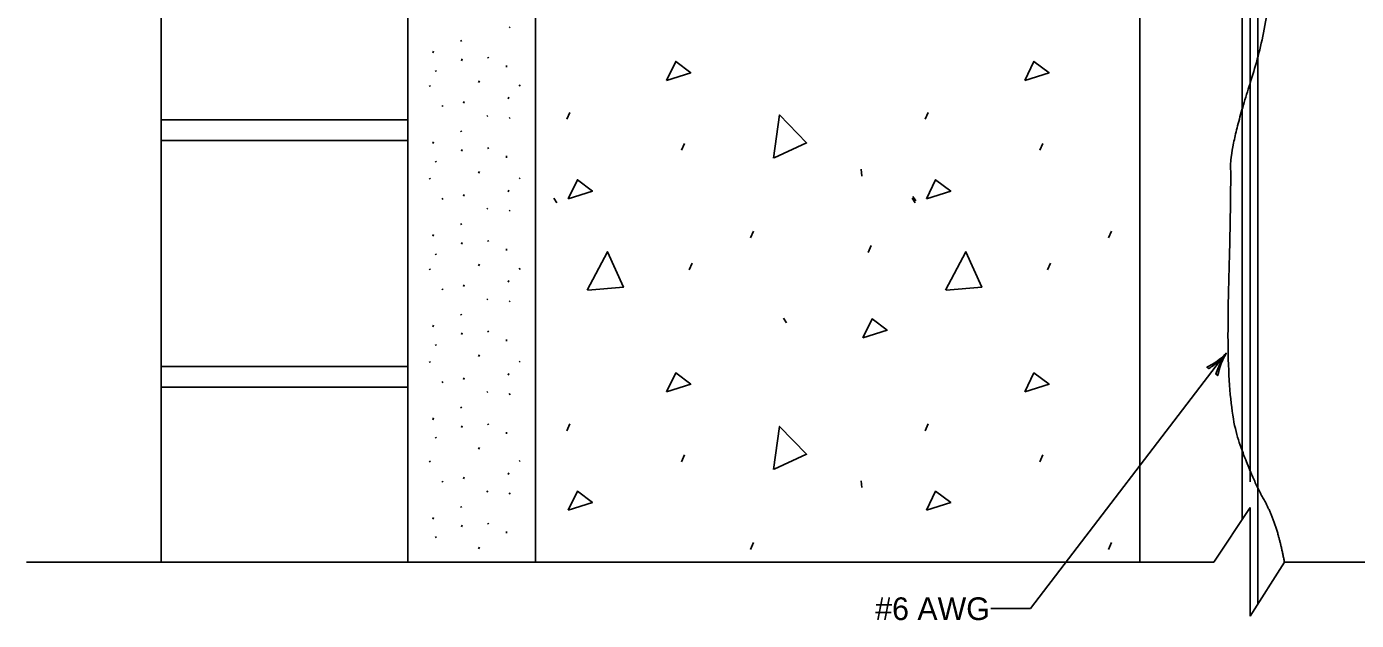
# Model space of a CAD drawing. Extents: x 10099 to 10284, y 10005 to 10185.
# Drawn here: x 10203.12 to 10242.19, y 10078.98 to 10096.42 of the extents above; entities that cross this region are included whole.
import ezdxf

# ---------------------------------------------------------------- set-up
doc = ezdxf.new("R2010")
doc.units = 0
for name, color, linetype in [('Level 46', 7, 'Continuous'), ('Level 5', 7, 'Continuous'), ('Level 6', 7, 'Continuous')]:
    doc.layers.add(name, color=color, linetype=linetype)

msp = doc.modelspace()

# ---------------------------------------------------------------- linework, layer by layer
at = {"layer": 'Level 46'}
for p, q in [((10239.074, 10083.046), (10239.074, 10161.024)), ((10207.074, 10122.686), (10207.074, 10080.693)), ((10214.324, 10122.686), (10214.324, 10080.693)), ((10218.074, 10122.686), (10218.074, 10080.693)), ((10217.302, 10096.418), (10217.325, 10096.384)), ((10215.879, 10096.023), (10215.901, 10095.99)), ((10215.054, 10095.651), (10215.076, 10095.701)), ((10215.897, 10095.423), (10215.919, 10095.473)), ((10216.667, 10095.531), (10216.689, 10095.497)), ((10217.217, 10095.284), (10217.222, 10095.234)), ((10215.134, 10095.137), (10215.157, 10095.103)), ((10216.402, 10094.779), (10216.424, 10094.829)), ((10214.959, 10094.698), (10214.981, 10094.665)), ((10217.596, 10094.711), (10217.618, 10094.677)), ((10215.331, 10094.107), (10215.354, 10094.073)), ((10215.953, 10094.172), (10215.975, 10094.222)), ((10217.268, 10094.299), (10217.29, 10094.349)), ((10207.074, 10093.686), (10214.324, 10093.686)), ((10216.646, 10093.816), (10216.669, 10093.783)), ((10217.302, 10093.756), (10217.325, 10093.723)), ((10218.991, 10093.7), (10219.08, 10093.9)), ((10229.519, 10093.7), (10229.608, 10093.9)), ((10215.879, 10093.362), (10215.901, 10093.329)), ((10207.074, 10093.078), (10214.324, 10093.078)), ((10215.054, 10092.989), (10215.076, 10093.039)), ((10216.667, 10092.869), (10216.689, 10092.836)), ((10222.366, 10092.79), (10222.454, 10092.99)), ((10232.893, 10092.79), (10232.982, 10092.99)), ((10215.134, 10092.475), (10215.157, 10092.442)), ((10215.897, 10092.762), (10215.919, 10092.812)), ((10217.217, 10092.623), (10217.222, 10092.573)), ((10216.402, 10092.118), (10216.424, 10092.168)), ((10227.644, 10092.232), (10227.666, 10092.033)), ((10214.959, 10091.972), (10214.981, 10091.939)), ((10217.596, 10091.985), (10217.618, 10091.951)), ((10215.331, 10091.381), (10215.354, 10091.347)), ((10215.953, 10091.446), (10215.975, 10091.495)), ((10217.268, 10091.573), (10217.29, 10091.623)), ((10218.614, 10091.385), (10218.702, 10091.251)), ((10229.141, 10091.385), (10229.23, 10091.251)), ((10229.159, 10091.435), (10229.248, 10091.302)), ((10216.646, 10091.09), (10216.669, 10091.057)), ((10217.302, 10091.03), (10217.325, 10090.997)), ((10215.879, 10090.636), (10215.901, 10090.603)), ((10215.054, 10090.263), (10215.076, 10090.313)), ((10216.667, 10090.143), (10216.689, 10090.11)), ((10224.386, 10090.215), (10224.475, 10090.415)), ((10234.913, 10090.215), (10235.002, 10090.415)), ((10215.134, 10089.749), (10215.157, 10089.716)), ((10215.897, 10090.036), (10215.919, 10090.086)), ((10217.217, 10089.896), (10217.222, 10089.846)), ((10227.849, 10089.789), (10227.938, 10089.989)), ((10216.402, 10089.392), (10216.424, 10089.442)), ((10222.588, 10089.279), (10222.676, 10089.479)), ((10233.115, 10089.279), (10233.204, 10089.479)), ((10214.959, 10089.311), (10214.981, 10089.277)), ((10217.268, 10088.912), (10217.29, 10088.962)), ((10217.596, 10089.323), (10217.618, 10089.29)), ((10215.331, 10088.72), (10215.354, 10088.686)), ((10215.953, 10088.784), (10215.975, 10088.834)), ((10216.646, 10088.429), (10216.669, 10088.396)), ((10217.302, 10088.369), (10217.325, 10088.336)), ((10215.879, 10087.975), (10215.901, 10087.942)), ((10225.363, 10087.858), (10225.452, 10087.725)), ((10215.054, 10087.602), (10215.076, 10087.652)), ((10215.897, 10087.375), (10215.919, 10087.425)), ((10216.667, 10087.482), (10216.689, 10087.449)), ((10215.134, 10087.088), (10215.157, 10087.055)), ((10217.217, 10087.235), (10217.222, 10087.185)), ((10216.402, 10086.731), (10216.424, 10086.781)), ((10232.617, 10079.33), (10238.328, 10086.789)), ((10207.074, 10086.436), (10214.324, 10086.436)), ((10214.959, 10086.585), (10214.981, 10086.551)), ((10217.268, 10086.186), (10217.29, 10086.236)), ((10217.596, 10086.597), (10217.618, 10086.564)), ((10207.074, 10085.828), (10214.324, 10085.828)), ((10215.331, 10085.993), (10215.354, 10085.96)), ((10215.953, 10086.058), (10215.975, 10086.108)), ((10216.646, 10085.703), (10216.669, 10085.67)), ((10217.302, 10085.643), (10217.325, 10085.61)), ((10215.879, 10085.249), (10215.901, 10085.216)), ((10215.054, 10084.876), (10215.076, 10084.926)), ((10215.897, 10084.649), (10215.919, 10084.699)), ((10216.667, 10084.756), (10216.689, 10084.723)), ((10218.991, 10084.55), (10219.08, 10084.75)), ((10229.519, 10084.55), (10229.608, 10084.75)), ((10215.134, 10084.362), (10215.157, 10084.329)), ((10217.217, 10084.509), (10217.222, 10084.459)), ((10216.402, 10084.005), (10216.424, 10084.055)), ((10214.959, 10083.664), (10214.981, 10083.631)), ((10217.596, 10083.677), (10217.618, 10083.643)), ((10222.366, 10083.64), (10222.454, 10083.84)), ((10232.893, 10083.64), (10232.982, 10083.84)), ((10215.953, 10083.138), (10215.975, 10083.187)), ((10217.268, 10083.265), (10217.29, 10083.315)), ((10215.331, 10083.073), (10215.354, 10083.039)), ((10216.646, 10082.782), (10216.669, 10082.749)), ((10217.302, 10082.722), (10217.325, 10082.689)), ((10227.644, 10083.082), (10227.666, 10082.883)), ((10215.879, 10082.328), (10215.901, 10082.295)), ((10215.054, 10081.955), (10215.076, 10082.005)), ((10238.009, 10080.693), (10239.077, 10082.293)), ((10239.077, 10082.293), (10239.077, 10079.106)), ((10215.897, 10081.728), (10215.919, 10081.778)), ((10216.667, 10081.835), (10216.689, 10081.802)), ((10217.217, 10081.588), (10217.222, 10081.538)), ((10215.134, 10081.441), (10215.157, 10081.408)), ((10216.402, 10081.084), (10216.424, 10081.134)), ((10224.386, 10081.065), (10224.475, 10081.265)), ((10234.913, 10081.065), (10235.002, 10081.265)), ((10203.118, 10080.693), (10238.009, 10080.693)), ((10239.077, 10079.106), (10240.078, 10080.693)), ((10240.078, 10080.693), (10274.776, 10080.693)), ((10231.448, 10079.33), (10232.617, 10079.33))]:
    msp.add_line(p, q, dxfattribs=at)
for points in [[(10221.926, 10094.844), (10222.192, 10095.399), (10222.636, 10095.066), (10221.926, 10094.844)], [(10232.454, 10094.844), (10232.72, 10095.399), (10233.164, 10095.066), (10232.454, 10094.844)], [(10225.067, 10092.56), (10225.243, 10093.829), (10226.038, 10093.008), (10225.087, 10092.568)], [(10219.036, 10091.369), (10219.302, 10091.924), (10219.746, 10091.591), (10219.036, 10091.369)], [(10229.563, 10091.369), (10229.83, 10091.924), (10230.274, 10091.591), (10229.563, 10091.369)], [(10219.591, 10088.68), (10220.19, 10089.812), (10220.656, 10088.768), (10219.613, 10088.68)], [(10230.118, 10088.68), (10230.718, 10089.812), (10231.184, 10088.768), (10230.14, 10088.68)], [(10227.694, 10087.281), (10227.96, 10087.836), (10228.404, 10087.503), (10227.694, 10087.281)], [(10238.371, 10086.83), (10238.328, 10086.789), (10238.285, 10086.748), (10238.23, 10086.695), (10238.165, 10086.646), (10238.11, 10086.604), (10238.062, 10086.567), (10238.018, 10086.541), (10237.97, 10086.511), (10237.925, 10086.484), (10237.879, 10086.456), (10237.836, 10086.434), (10237.801, 10086.416), (10237.854, 10086.376), (10237.893, 10086.4), (10237.93, 10086.424), (10237.968, 10086.452), (10238.005, 10086.479), (10238.05, 10086.514), (10238.087, 10086.54), (10238.132, 10086.581), (10238.17, 10086.616), (10238.213, 10086.656), (10238.252, 10086.695), (10238.285, 10086.731), (10238.311, 10086.761), (10238.339, 10086.792), (10238.371, 10086.83), (10238.336, 10086.777), (10238.303, 10086.725), (10238.258, 10086.657), (10238.223, 10086.59), (10238.198, 10086.54), (10238.171, 10086.489), (10238.15, 10086.438), (10238.124, 10086.371), (10238.105, 10086.323), (10238.087, 10086.273), (10238.068, 10086.212), (10238.122, 10086.17), (10238.132, 10086.219), (10238.148, 10086.289), (10238.163, 10086.339), (10238.182, 10086.405), (10238.202, 10086.47), (10238.223, 10086.522), (10238.25, 10086.587), (10238.268, 10086.634), (10238.293, 10086.683), (10238.319, 10086.731), (10238.345, 10086.78), (10238.371, 10086.83)], [(10221.926, 10085.694), (10222.192, 10086.249), (10222.636, 10085.916), (10221.926, 10085.694)], [(10232.454, 10085.694), (10232.72, 10086.249), (10233.164, 10085.916), (10232.454, 10085.694)], [(10225.067, 10083.41), (10225.243, 10084.679), (10226.038, 10083.858), (10225.087, 10083.418)], [(10219.036, 10082.219), (10219.302, 10082.774), (10219.746, 10082.441), (10219.036, 10082.219)], [(10229.563, 10082.219), (10229.83, 10082.774), (10230.274, 10082.441), (10229.563, 10082.219)]]:
    msp.add_lwpolyline(points, dxfattribs=at)
at = {"layer": 'Level 5'}
msp.add_open_spline([(10240.078, 10080.693), (10239.868, 10081.836), (10239.122, 10083.147), (10238.352, 10085.356), (10238.516, 10091.653), (10238.478, 10092.926), (10239.754, 10096.885), (10240.049, 10103.053), (10240.049, 10106.552), (10238.38, 10111.799), (10238.38, 10114.837), (10238.38, 10116.77), (10238.478, 10124.596), (10238.639, 10126.23), (10239.378, 10127.385), (10240.434, 10129.135), (10241.49, 10131.676), (10241.912, 10133.59), (10242.053, 10137.913), (10242.017, 10140.752), (10242.088, 10142.435), (10242.088, 10143.392), (10241.912, 10144.217), (10241.5, 10144.405)], degree=2, dxfattribs=at)
at = {"layer": 'Level 6'}
for p, q in [((10235.834, 10126.686), (10235.834, 10080.693)), ((10238.834, 10126.686), (10238.834, 10081.93)), ((10239.3, 10126.686), (10239.3, 10079.46))]:
    msp.add_line(p, q, dxfattribs=at)

# ---------------------------------------------------------------- texts
at = {"layer": 'Level 46'}
msp.add_text('#6 AWG', height=0.6667, dxfattribs=at).set_placement((10228.054, 10078.989))

doc.saveas('drawing.dxf')
